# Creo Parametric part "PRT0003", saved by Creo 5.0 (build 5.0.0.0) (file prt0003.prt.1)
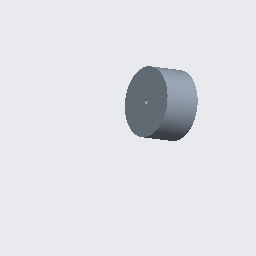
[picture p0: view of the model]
Units: Inch lbm Second (Pro/E Default); INCH, POUND, SECS

Created from: INLBS_PART_SOLID.PRT

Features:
  1. datum plane "RIGHT"
  2. datum plane "TOP"
  3. datum plane "FRONT"
  4. coordinate system
  5. sketch "Sketch 1"
  6. extrusion "Extrude 1"

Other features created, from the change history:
  sketch "Sketch 1"

Surfaces: 2 plane, 2 cylinder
